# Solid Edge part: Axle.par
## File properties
Title: Axle
Subject: Wheel Assembly
Author: kiyo
Keywords: Axle
Comments: Axle 30mm Diameter
Template: metric.par
Last saved by: edge
Revision: 36
Application: Solid Edge
File Size: 0
Number of Sheets: 0
Number of Objects: 0
Username: kiyo
文書内容のタイプ: 0
Material: Steel
Face Style: Model Default
Coef. of Thermal Exp: 0.0
Thermal Conductivity: 0.0
Specific Heat: 0.0
Modulus of Elasticity: 0.0
Poisson's Ratio: 0.0
Yield Stress: 0.0
Ultimate Stress: 0.0
Elongation: 0.0
Category: Machined Cylindrical
Manager: Brian Little
Company: Wheels R Us
Density: 7800
Accuracy: 0.99
Document Number: A-101
Revision: 1
Project Name: Trolley Wheel Assembly
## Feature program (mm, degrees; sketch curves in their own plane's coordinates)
sketch for "unnamed RevolvedProtrusion 1" plane through (0, 0, 0) normal (0, -1, 0) x-axis (1, 0, 0)
  line (-48.8311, 5.6541) -> (-48.8311, 20.6541)
  line (-48.8311, 20.6541) -> (-43.8311, 20.6541)
  line (-43.8311, 20.6541) -> (-43.8311, 19.6541)
  line (-43.8311, 19.6541) -> (-41.8311, 19.6541)
  line (-41.8311, 19.6541) -> (-41.8311, 20.6541)
  line (-41.8311, 20.6541) -> (8.1689, 20.6541)
  line (8.1689, 20.6541) -> (8.1689, 15.6541)
  line (8.1689, 15.6541) -> (23.1689, 15.6541)
  line (23.1689, 15.6541) -> (23.1689, 14.6541)
  line (23.1689, 14.6541) -> (25.1689, 14.6541)
  line (25.1689, 14.6541) -> (25.1689, 15.6541)
  line (25.1689, 15.6541) -> (30.1689, 15.6541)
  line (30.1689, 15.6541) -> (30.1689, 5.6541)
  line (30.1689, 5.6541) -> (-48.8311, 5.6541)
revolve "unnamed RevolvedProtrusion 1" add finite 360 deg about sketch line (-53.2645, 5.6541) -> (-59.4326, 5.6541)
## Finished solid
Body 1: solid body, 13 faces, 12 edges, 0 vertices.
  Faces by surface: plane 7, cylinder 6
  Edges by curve: circle 12
Bounding box of the edges (mm): 79.000 x 30.000 x 30.000, from (-48.8311, -15, -9.3459) to (30.1689, 15, 20.6541).
Cylindrical faces by radius (mm): R9 x1, R10 x2, R14 x1, R15 x2
Planar faces by outward normal: +x 4, -x 3
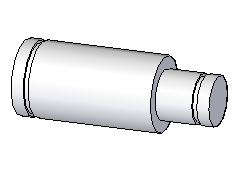
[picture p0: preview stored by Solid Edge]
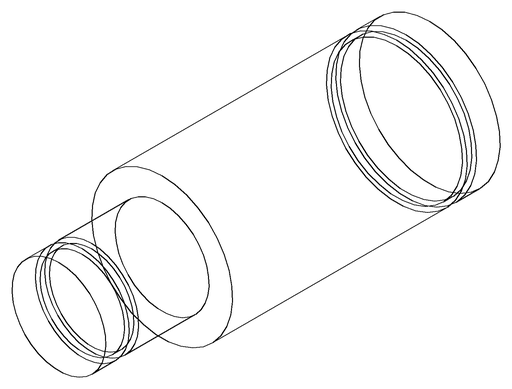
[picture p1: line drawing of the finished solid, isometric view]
